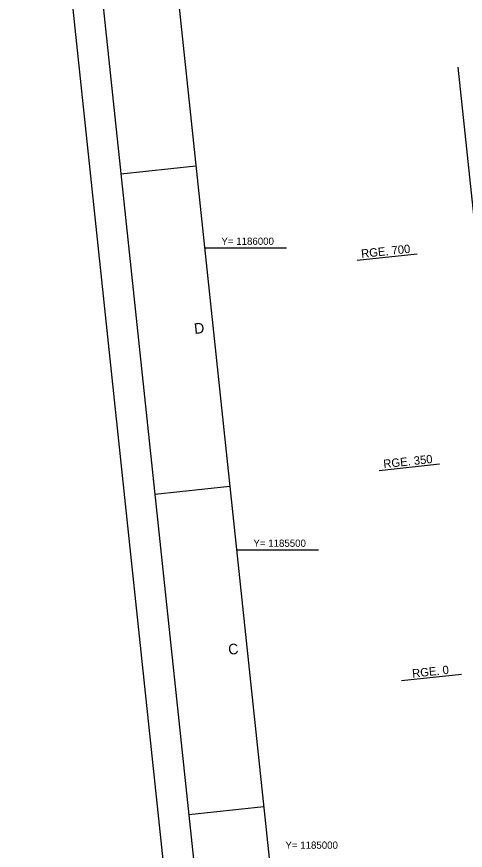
# Model space of a CAD drawing. Extents: x 338488 to 343222, y 1183896 to 1187741.
# Drawn here: x 338488 to 339232, y 1185002 to 1186383 of the extents above; entities that cross this region are included whole.
import ezdxf

# ---------------------------------------------------------------- set-up
doc = ezdxf.new("R2010")
doc.units = 0
for name, color, linetype in [('G-ANNO-NPLT', 7, 'Continuous'), ('G-ANNO-TTLB', 7, 'Continuous'), ('V-ALGN-TEXT', 7, 'Continuous'), ('V-ANNO-MATC', 7, 'Continuous'), ('V-TOPO-COOR-STAT', 7, 'Continuous')]:
    doc.layers.add(name, color=color, linetype=linetype)

msp = doc.modelspace()

# ---------------------------------------------------------------- linework, layer by layer
at = {"layer": 'G-ANNO-NPLT'}
msp.add_lwpolyline([(338488.3, 1187277.4), (342863.7, 1187741.2), (343222.1, 1184360.2), (338846.6, 1183896.4)], close=True, dxfattribs=at)
at = {"layer": 'G-ANNO-TTLB'}
for p, q in [((338661, 1186122.4), (338785.3, 1186135.6)), ((338717.2, 1185592.1), (338841.5, 1185605.3)), ((338773.4, 1185061.8), (338897.7, 1185074.9))]:
    msp.add_line(p, q, dxfattribs=at)
for points in [[(338891.1, 1183951.4), (343167.1, 1184404.6), (342819.3, 1187686.2), (338543.3, 1187233)], [(342774.8, 1187631.3), (338672.8, 1187196.4), (339010.1, 1184014.3), (343112.1, 1184449.1)]]:
    msp.add_lwpolyline(points, close=True, dxfattribs=at)
at = {"layer": 'V-ALGN-TEXT'}
for p, q in [((339052.2, 1185979.7), (339151.7, 1185990.2)), ((339089.1, 1185631.6), (339188.6, 1185642.2)), ((339126, 1185283.6), (339225.4, 1185294.1))]:
    msp.add_line(p, q, dxfattribs=at)
at = {"layer": 'V-ANNO-MATC'}
msp.add_line((339356.5, 1185006.3), (339219.5, 1186299.1), dxfattribs=at)
at = {"layer": 'V-TOPO-COOR-STAT'}
for p, q in [((338799.6, 1186000), (338935.4, 1186000)), ((338852.6, 1185500), (338988.4, 1185500))]:
    msp.add_line(p, q, dxfattribs=at)

# ---------------------------------------------------------------- texts
at = {"layer": 'G-ANNO-TTLB'}
for s, p in [('D', (338783.1, 1185857.4)), ('C', (338839.6, 1185326.1))]:
    msp.add_text(s, height=17.5, rotation=6.0506, dxfattribs=at).set_placement(p)
at = {"layer": 'V-ALGN-TEXT'}
for s, p in [('RGE. 700', (339059.7, 1185983.3)), ('RGE. 350', (339096.5, 1185635.2)), ('RGE. 0', (339144.2, 1185288.3))]:
    msp.add_text(s, height=13.92, rotation=6.0506, dxfattribs=at).set_placement(p)
at = {"layer": 'V-TOPO-COOR-STAT'}
for s, p in [('Y= 1186000', (338827.5, 1186005)), ('Y= 1185500', (338880.5, 1185505)), ('Y= 1185000', (338933.5, 1185005))]:
    msp.add_text(s, height=12, dxfattribs=at).set_placement(p)

doc.saveas('drawing.dxf')
